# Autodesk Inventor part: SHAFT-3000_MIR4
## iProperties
Created: 2007-08
Part Number: SHAFT-3000_MIR4
Material: Stainless Steel
Document SubType Name: Modeling
Density: 8.08 g/cm^3
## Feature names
1. Derived Body1 [Tagging]
